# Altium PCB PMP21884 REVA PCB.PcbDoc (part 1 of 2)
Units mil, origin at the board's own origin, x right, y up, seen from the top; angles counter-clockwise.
Board outline 2378 x 1724 mil, 4 copper layers (Top Layer, Signal Layer 1, Signal Layer 2, Bottom Layer), stack 61.6 mil thick; 76 components, 35 nets, 187 pads, 142 vias.
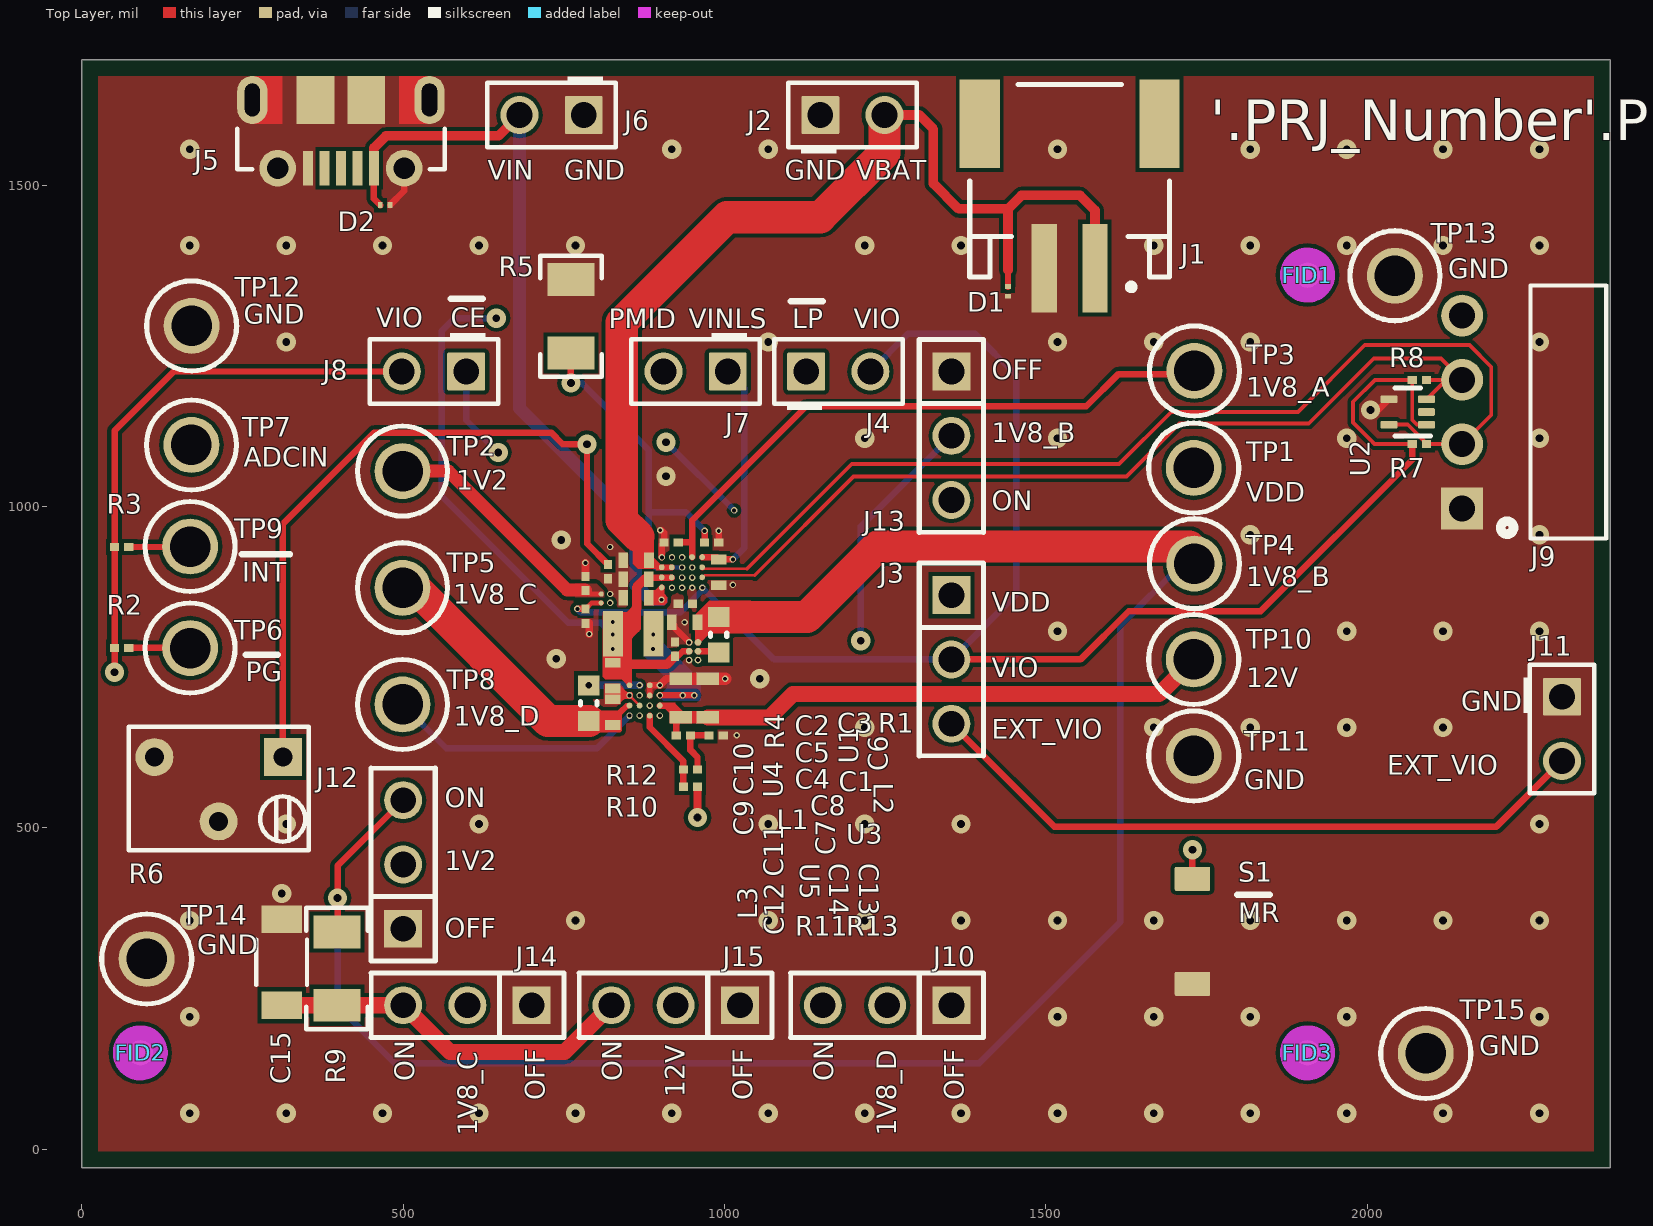
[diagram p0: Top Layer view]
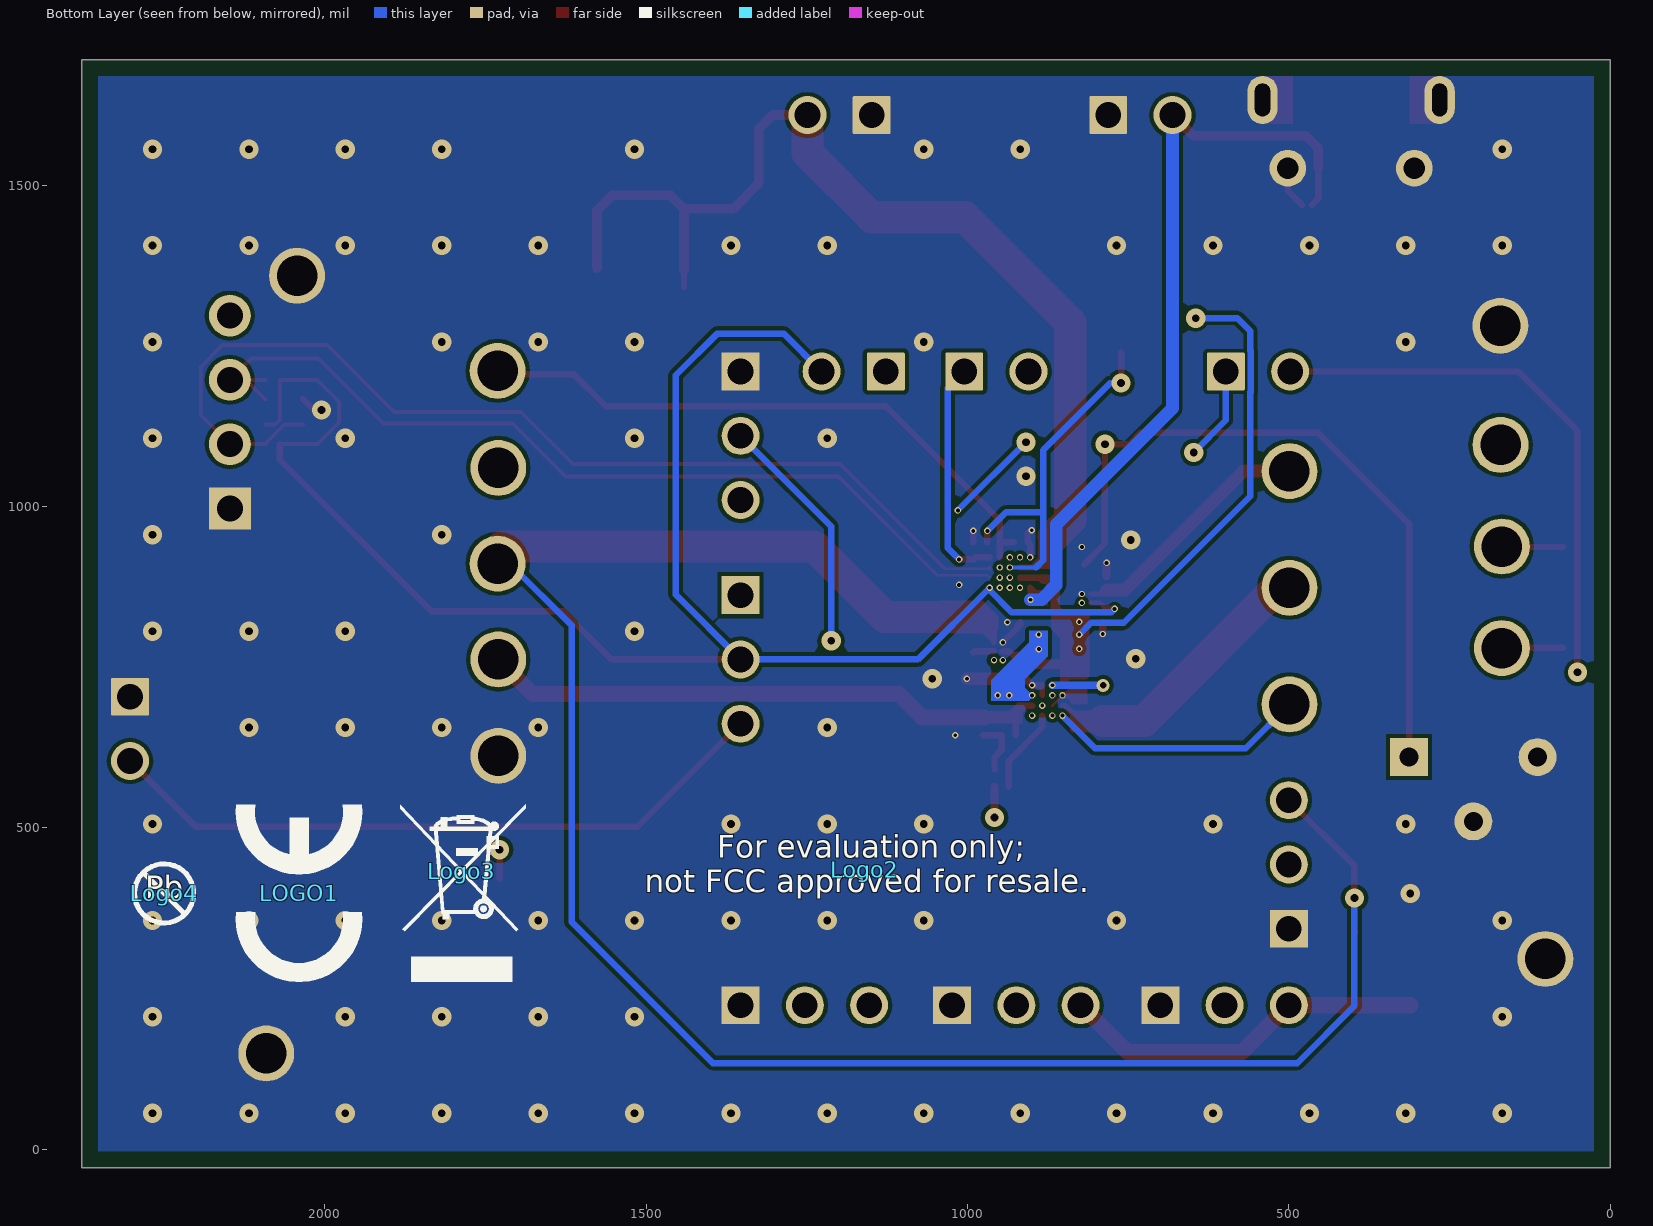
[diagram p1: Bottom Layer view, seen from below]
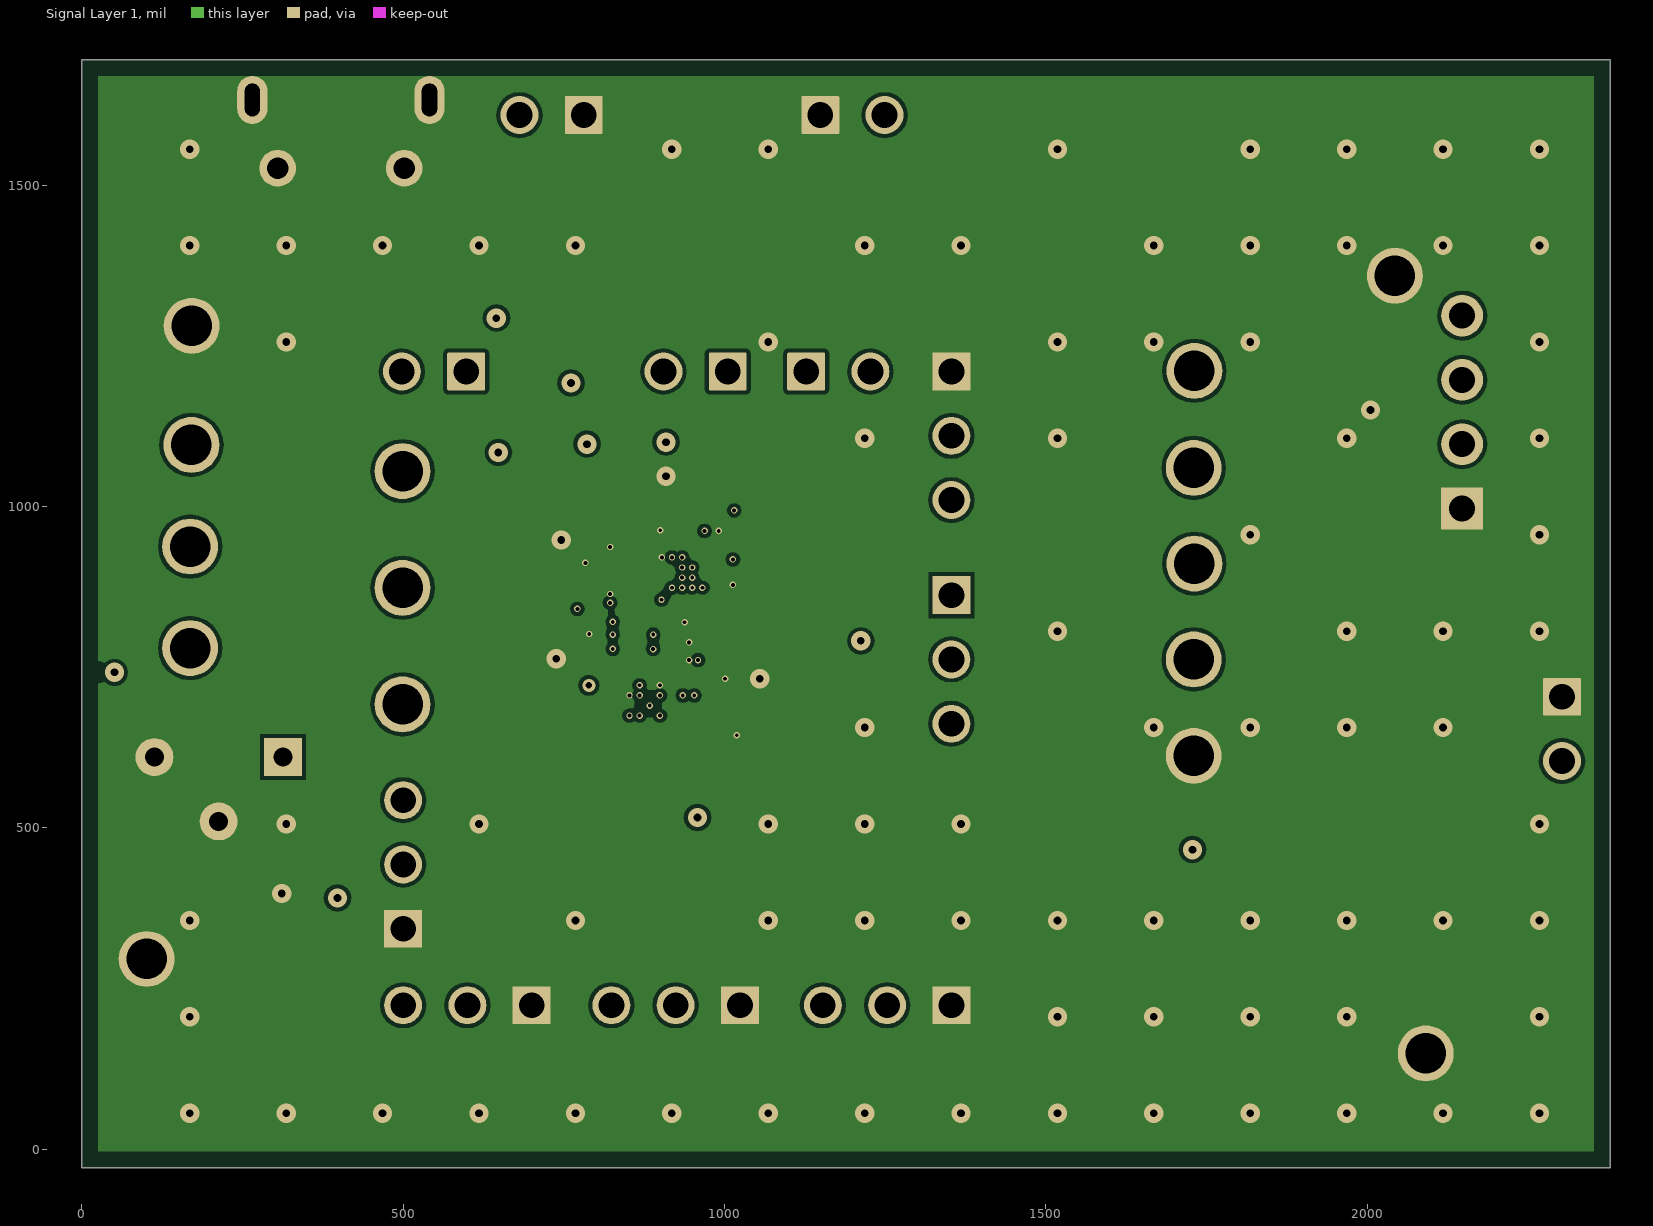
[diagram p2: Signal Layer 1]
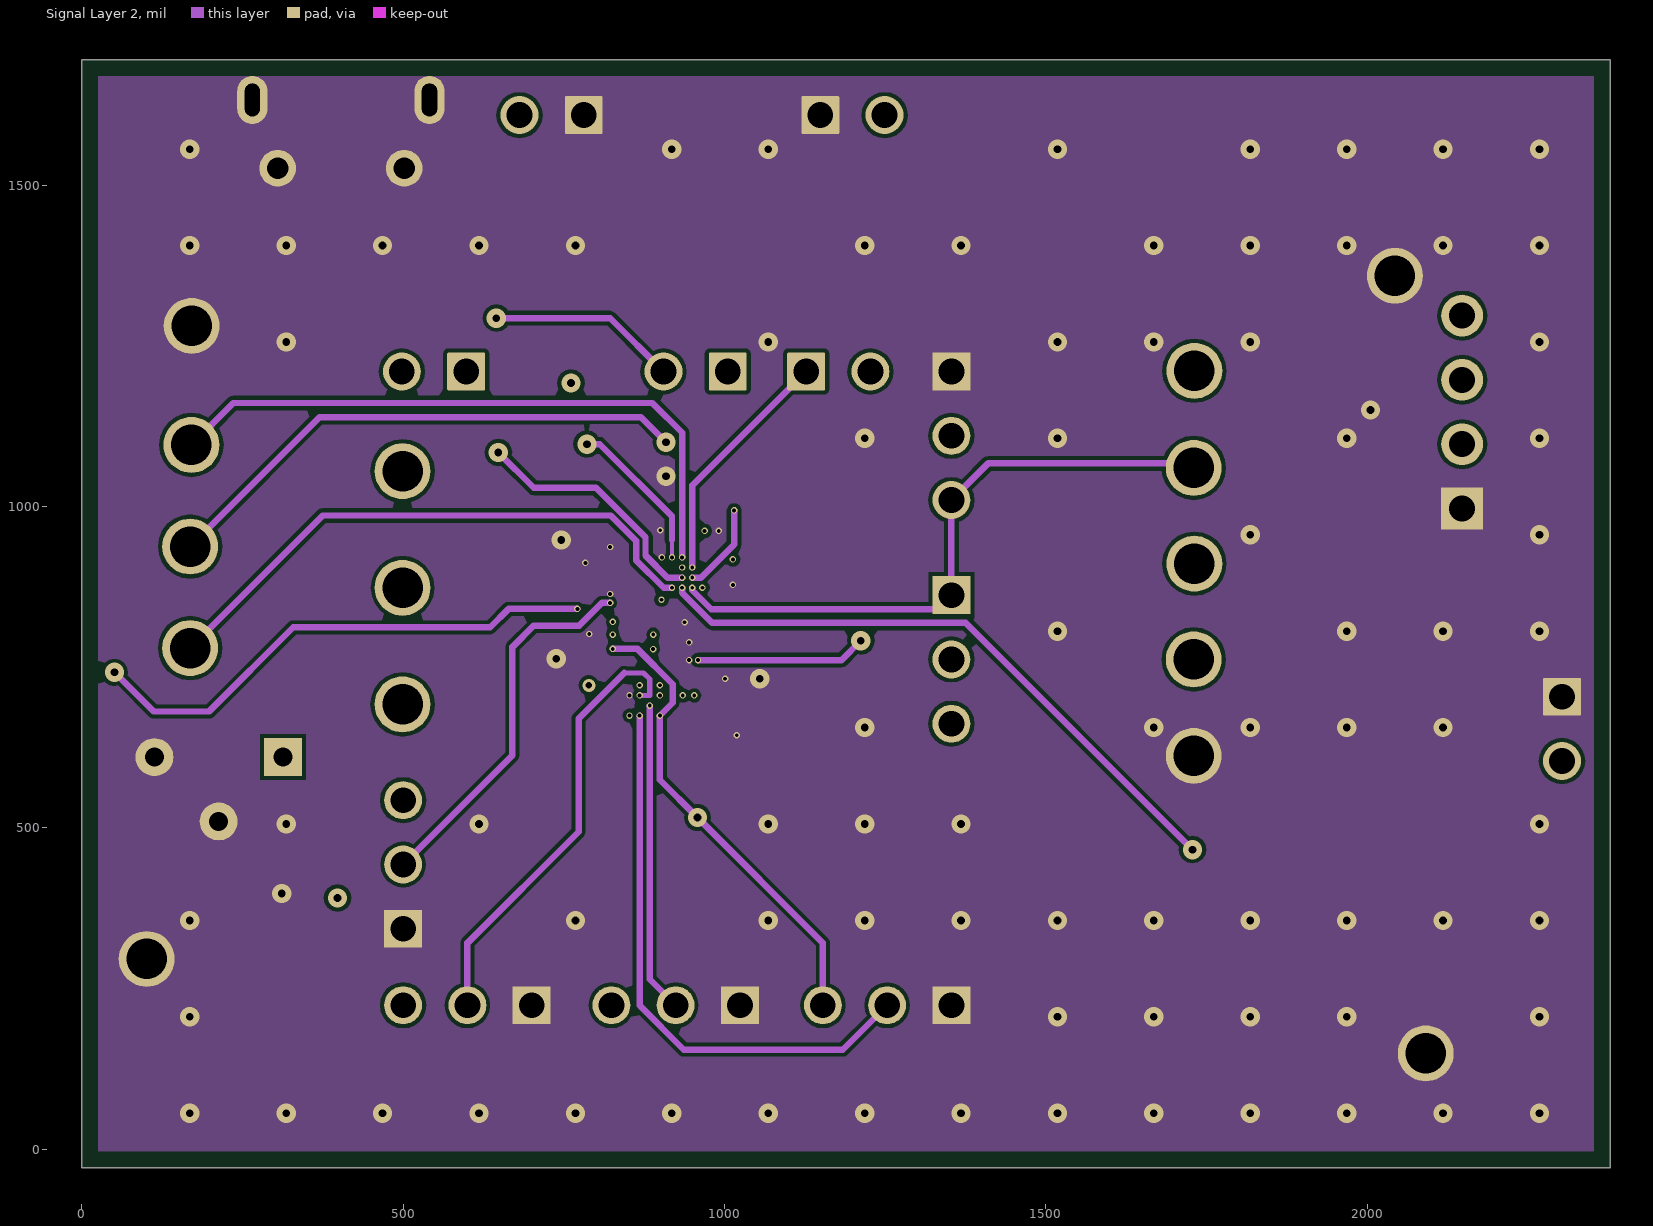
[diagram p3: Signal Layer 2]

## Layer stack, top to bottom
Top Solder: solder mask 0.4, Solder Resist, Dk 3.5
Top Layer: signal copper 1.4
Dielectric 1: prepreg 8, FR-4, Dk 4.2
Signal Layer 1: signal copper 1.4
Dielectric 2: core 40, FR-4, Dk 4.2
Signal Layer 2: signal copper 1.4
Dielectric 3: prepreg 8, FR-4, Dk 4.2
Bottom Layer: signal copper 1.4
Bottom Solder: solder mask 0.4, Solder Resist, Dk 3.5

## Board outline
0,-29 2378,-29 2378,1695 0,1695

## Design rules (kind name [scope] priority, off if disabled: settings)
AcuteAngle [All] p1: minimum=4.50000000000000E+0001 checktracksonly=FALSE
AssemblyTestPointUsage [All] p1: valid=2
BoardOutlineClearance BoardOutlineClearance_MountingHoles [OnCopper and InComponentClass('Mounting Holes')] p1: gap=25 ignorepadtopadclearanceinfootprint=FALSE
BoardOutlineClearance BoardOutlineClearance_Poly [OnCopper and InPoly] p2: gap=25 ignorepadtopadclearanceinfootprint=FALSE
BoardOutlineClearance [OnCopper and Not InComponentClass('Logo') and not InComponentClass('FiducialMark') and not InRegion(1000,500,4000,800)] p3: gap=25 ignorepadtopadclearanceinfootprint=FALSE
Clearance Clearance_GND [All vs InNet('GND') And InPolygon] p1: gap=6 ignorepadtopadclearanceinfootprint=FALSE
Clearance Clearance_Fiducial [InComponent('FID1') Or InComponent('FID2') Or InComponent('FID3')] p2: gap=0 ignorepadtopadclearanceinfootprint=FALSE
Clearance Clearance_SmallBGA [All vs InRegionRelative(800, 842, 830, 870) Or InRegionRelative(937, 754, 965, 796)] p3: gap=3.3 ignorepadtopadclearanceinfootprint=FALSE
Clearance Clearance_Keepouts [((IsTrack Or IsArc) And Not InPoly) And IsFree and IsKeepOut vs ((IsTrack Or IsArc) And Not InPoly) And IsFree and IsKeepOut] p4: gap=0 ignorepadtopadclearanceinfootprint=FALSE
Clearance Clearance_Poly [InPolygon] p5: gap=4 ignorepadtopadclearanceinfootprint=FALSE
Clearance [All] p6: gap=4 ignorepadtopadclearanceinfootprint=FALSE except(6: Arc-Hole Track-Hole SMDPad-Hole THPad-Hole Via-Hole Fill-Hole Poly-Hole Region-Hole Text-Hole)
ComponentClearance ComponentClearance_BGA [HasParameterValue('CompType', 'IC')] p1: gap=4 collisioncheckmode=3 verticalgap=10 showdistances=TRUE
ComponentClearance ComponentClearance_Cap-Resistor [HasParameterValue('CompType', 'Resistor') Or HasParameterValue('CompType', 'Capacitor') Or HasParameterValue('CompType', 'Inductor')] p2: gap=4 collisioncheckmode=3 verticalgap=0 showdistances=TRUE
ComponentClearance ComponentClearance_MountingHoles_FiducialMarks [InComponentClass('Mounting Holes') vs InComponentClass('FiducialMark')] p3: gap=50 collisioncheckmode=3 verticalgap=10 showdistances=FALSE
ComponentClearance ComponentClearance_Shunt [InComponentClass('Header') vs InComponentClass('Shunt')] p4: gap=0 collisioncheckmode=3 verticalgap=0 showdistances=FALSE
ComponentClearance ComponentClearance_Logo [InComponentClass('Logo')] p5: gap=50 collisioncheckmode=3 verticalgap=10 showdistances=FALSE
ComponentClearance ComponentClearance_ScrewToNut [(HasFootprint('NY PMS 440 0025 PH')) vs (HasFootprint('Keystone_1902C'))] p6: gap=5 collisioncheckmode=3 verticalgap=10 showdistances=FALSE
ComponentClearance ComponentClearance_MountingHoles [InComponentClass('Mounting Holes')] p7: gap=250 collisioncheckmode=3 verticalgap=100000 showdistances=FALSE
ComponentClearance ComponentClearance_SmallPassives [HasFootprint('0201*') or HasFootprint('0402*') or HasFootprint('0508') or HasFootprint('0603*') or HasFootprint('0612') or HasFootprint('0805*') or HasFootprint('0815*') or HasFootprint('0830*') or HasFootprint('1206*') or HasFootprint('1210*') or HasFootprint('1808*') or HasFootprint('1812*') or HasFootprint('1825*') or HasFootprint('2010*') or HasFootprint('2220*') or HasFootprint('2225*') or HasFootprint('2512*') or HasFootprint('2728*') or HasFootprint('3518*') vs HasFootprint('0201*') or HasFootprint('0402*') or HasFootprint('0508') or HasFootprint('0603*') or HasFootprint('0612') or HasFootprint('0805*') or HasFootprint('0815*') or HasFootprint('0830*') or HasFootprint('1206*') or HasFootprint('1210*') or HasFootprint('1808*') or HasFootprint('1812*') or HasFootprint('1825*') or HasFootprint('2010*') or HasFootprint('2220*') or HasFootprint('2225*') or HasFootprint('2512*') or HasFootprint('2728*') or HasFootprint('3518*')] p8: gap=2 collisioncheckmode=3 verticalgap=10 showdistances=FALSE
ComponentClearance ComponentClearance_THtoSMT [IsThruComponent vs IsSMTComponent] p9: gap=15 collisioncheckmode=3 verticalgap=30 showdistances=FALSE
ComponentClearance ComponentClearance_THtoTH [IsThruComponent vs IsThruComponent] p10: gap=15 collisioncheckmode=3 verticalgap=30 showdistances=FALSE
ComponentClearance [All] p11: gap=2 collisioncheckmode=3 verticalgap=10 showdistances=FALSE
DiffPairsRouting [All] p1: maxlimit=100 minlimit=10 mostfreqgap=10 toplayer_minwidth=15 toplayer_maxwidth=15 toplayer_prefwidth=15 midlayer1_minwidth=15 midlayer1_maxwidth=15 midlayer1_prefwidth=15 midlayer2_minwidth=15 midlayer2_maxwidth=15 midlayer2_prefwidth=15 bottomlayer_minwidth=15 bottomlayer_maxwidth=15 bottomlayer_prefwidth=15 maxuncoupledlength=1000
FabricationTestPointUsage TestPointUsage [All] p1: valid=2 allowmultiple=FALSE
FabricationTestpoint Testpoint [All] p1: side=3 testpointundercomponent=TRUE minsize=40 maxsize=100 preferedsize=60 minholesize=0 maxholesize=40 preferedholesize=32 testpointgrid=1 allowsidetop=TRUE allowsidebottom=TRUE usegrid=TRUE gridtolerance=0.01
FanoutControl Fanout_LCC [IsLCC] p1: bgadir=Out bgaviamode=Centered fanoutstyle=Auto fanoutdirection=Alternating viagrid=1 // Fanout_LCC (Default Rule)
FanoutControl Fanout_BGA [IsBGA] p2: bgadir=Out bgaviamode=Centered fanoutstyle=Auto fanoutdirection=Alternating viagrid=1 // Fanout_BGA (Default Rule)
FanoutControl Fanout_Default [All] p4: bgadir=Out bgaviamode=Centered fanoutstyle=Auto fanoutdirection=Alternating viagrid=1 // Fanout_Default (Default Rule)
FanoutControl Fanout_Small [(CompPinCount < 5)] p5: bgadir=Out bgaviamode=Centered fanoutstyle=Auto fanoutdirection=OutThenIn viagrid=1 // Fanout_Small (Default Rule)
HoleSize [All] p1: absolutevalues=TRUE maxlimit=251 minlimit=5 maxpercent=80.000 minpercent=20.000
HoleToHoleClearance [All] p1: gap=6 allowstackedmicrovias=TRUE
MinimumAnnularRing MinimumAnnularRing_ThermalPadVias [IsVia and InAnyComponent] p1: minimumring=5.91
MinimumAnnularRing [All] p2: minimumring=1.5
MinimumSolderMaskSliver MinimumSolderMaskSliver_Logo [InComponentClass('Logo') vs InComponentClass('Logo')] p1: minsoldermaskwidth=0.7
MinimumSolderMaskSliver [All] p2: minsoldermaskwidth=1.5
PlaneClearance PlaneClearance_GND [InNet('GND')] p1: clearance=6
PlaneClearance PlaneClearance_GND_1 [InNet('GND') And InPolygon] p2: clearance=6
PlaneClearance [All] p3: clearance=15
PlaneConnect [All] p1: planeconnectstyle=Direct reliefexpansion=10 reliefentries=4 reliefconductorwidth=10 reliefairgap=10
PolygonConnect [All] p1: connectstyle=Direct reliefconductorwidth=10 reliefentries=4 polygonreliefangle="90 Angle" airgapwidth=10
RoutingVias ThermalPadVias [IsVia and InAnyComponent] p1: holewidth=7.87 width=19.68 viastyle="Through Hole" minholewidth=7.87 minwidth=19.68 maxholewidth=12.99 maxwidth=23.62
RoutingVias [All] p2: holewidth=16 width=34 viastyle="Through Hole" minholewidth=6 minwidth=10 maxholewidth=40 maxwidth=65
SilkToBoardRegionClearance [Not ((IsComment or IsDesignator) And (Hide <> 'False')) and not InRegion(1000,500,4000,800)] p1:
SilkToSilkClearance SilkToSilkClearance_Pb-FreeLogo [(HasFootprint('Pb-Free_Overlay_Medium') OR HasFootprint('Pb-Free_Overlay_Small')) vs (HasFootprint('Pb-Free_Overlay_Medium') OR HasFootprint('Pb-Free_Overlay_Small'))] p1: silktosilkclearance=0
SilkToSilkClearance [All] p2: silktosilkclearance=0
SilkToSolderMaskClearance SilkToComponentPadClearance [IsPad and InAnycomponent] p1: minsilkscreentomaskgap=0 clearancetoexposedcopper=TRUE
SilkToSolderMaskClearance "Silk to Solder Mask Opening" [All] p2: minsilkscreentomaskgap=0 clearancetoexposedcopper=FALSE
SolderMaskExpansion [All] p1: expansion=1.97
Width [All] p1: maxlimit=100 minlimit=4 preferedwidth=10 checkconnectedcopper=TRUE
13 further rules are at their usual default settings.

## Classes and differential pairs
component class Header: J2 J3 J4 J6 J7 J8 J10 J11 J12 J13 J14 J15
component class FiducialMark: FID1 FID2 FID3

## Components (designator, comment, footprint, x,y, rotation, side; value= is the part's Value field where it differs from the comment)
C1 "GRM035R60J475ME15D" 0201L 939,848.61 r180 top value=4.7uF
C2 "CL05A105MP5NNNC" 0402S 862.43,916.19 r180 top value=1uF
C3 "CL03A225MQ3CRNC" 0201L 917,944.11 r0 top value=2.2uF
C4 "CL05A105KA5NQNC" 0402S 862.21,857.76 r180 top value=1uF
C5 "C1005X5R1A475M050BC" 0402S 862.21,886.76 r180 top value=4.7uF
C6 "CL05A105MP5NNNC" 0402S 991,897.61 r270 top value=1uF
C7 "GRM035R60J475ME15D" 0201L 923,778 r90 top value=4.7uF
C8 "GRM155R60J106ME15D" 0402S 938,820 r180 top value=10uF
C9 "GRM033R60J105MEA2D" 0201_033L 783.62,829.25 r270 top value=1uF
C10 "GRM033R60J105MEA2D" 0201_033L 783.62,880.3 r90 top value=1uF
C11 "GRM155R60J106ME15D" 0402S 825.99,736.92 r270 top value=10uF
C12 "GRM155R60J106ME15D" 0402S 826,680 r90 top value=10uF
C13 "GRM188R61E106MA73J" 0603S 974,702 r90 top value=10uF
C14 "GRM188R61E106MA73J" 0603S 932,702 r90 top value=10uF
C15 "CGA5L2X5R1H474K160AA" 1206_190 311,290.93 r90 top value=0.47uF
D1 "TPD1E6B06DPLR" DPL0002A 1441,1334.58 r90 top
D2 "TPD1E6B06DPLR" DPL0002A 472,1469 r180 top
FID1 "Fiducial" Fiducial10-20 1907,1360 r0 top
FID2 "Fiducial" Fiducial10-20 91,150 r0 top
FID3 "Fiducial" Fiducial10-20 1907,150 r0 top
J1 "S2B-PH-SM4-TB(LF)(SN)" JST_S2B-PH-SM4-TB 1537,1487 r180 top
J2 "PEC02SAAN" CONN_PEC02SAAN 1199,1609 r0 top
J3 "PEC03SAAN" CONN_PEC03SAAN 1353,762 r270 top
J4 "PEC02SAAN" CONN_PEC02SAAN 1177,1210 r0 top
J5 "105017-0001" CONN_105017-0001 403.2,1579.45 r180 top
J6 "PEC02SAAN" CONN_PEC02SAAN 731,1609 r180 top
J7 "PEC02SAAN" CONN_PEC02SAAN 955,1210 r180 top
J8 "PEC02SAAN" CONN_PEC02SAAN 548,1210 r180 top
J9 "22/05/3041" CONN_22-05-3041 2372,1147 r90 top
J10 "PEC03SAAN" CONN_PEC03SAAN 1253,224 r180 top
J11 "PEC02SAAN" CONN_PEC02SAAN 2303,654 r270 top
J12 "PEC03SAAN" CONN_PEC03SAAN 500,443 r90 top
J13 "PEC03SAAN" CONN_PEC03SAAN 1353,1110 r270 top
J14 "PEC03SAAN" CONN_PEC03SAAN 600,224 r180 top
J15 "PEC03SAAN" CONN_PEC03SAAN 924,224 r180 top
L1 "DFE201610E-100M=P2" DFE201610E 858,802 r180 top value=10uH
L2 "DFE18SANR47MG0L" 0603L 990.72,800.45 r90 top value=470nH
L3 "LQM18PN2R2MGHD" 0603L 789,694 r270 top value=2.2uH
LOGO1 "CE Mark" CE_Mark_5mm 2040,398 r90 bottom (schematic designator Logo1)
Logo2 "FCC disclaimer" FCC_disclaimer_stacked 1160,434.9 r180 bottom
Logo3 "WEEE logo" WEEE_Minimum 1787,432.45 r180 bottom
Logo4 "Pb-Free Symbol" Pb-Free_Overlay_Small 2250,398 r180 bottom
R1 "RC0201JR-0712KL" 0201L 979.98,944 r0 top value=12k
R2 "RC0201JR-0710KL" 0201L 62.02,780 r0 top value=10k
R3 "RC0201JR-0710KL" 0201L 62.02,937 r0 top value=10k
R4 "RC0201FR-0710KL" 0201L 818.62,898.63 r270 top value=10.0k
R5 "RC1206FR-0759KL" 1206 761,1296 r270 top value=59.0k
R6 "3266W-1-104LF" TRIM_3266W 313,610 r270 top value=100k
R7 "RC0201JR-0710KL" 0201L 2080.98,1097 r180 top value=10k
R8 "RC0201JR-0710KL" 0201L 2080.98,1197 r0 top value=10k
R9 "CRCW12066K04FKEA" 1206 397,281.09 r270 top value=6.04k
R10 "CRCW02010000Z0ED" 0201L 946.98,564 r0 top value=0
R11 "RC0201JR-07430KL" 0201L 935.98,644 r180 top value=430k
R12 "CRCW02010000Z0ED" 0201L 946.98,591 r180 top value=0
R13 "RC0201FR-0782KL" 0201L 987,644 r180 top value=82.0k
S1 "TL1015AF160QG" SW_TL1015AF160QG 1728,339 r90 top
TP1 "5010" Keystone5010 1730,1060 r0 top
TP2 "5010" Keystone5010 499,1055 r0 top
TP3 "5010" Keystone5010 1731,1211 r0 top
TP4 "5010" Keystone5010 1731,911 r0 top
TP5 "5010" Keystone5010 499,873.5 r0 top
TP6 "5012" Keystone5012 168.6,779.72 r180 top
TP7 "5012" Keystone5012 170.6,1095.72 r180 top
TP8 "5010" Keystone5010 499,692 r0 top
TP9 "5012" Keystone5012 168.6,937.72 r180 top
TP10 "5010" Keystone5010 1730,762 r0 top
TP11 "5011" Keystone5011 1730,612 r0 top
TP12 "5011" Keystone5011 171,1281 r0 top
TP13 "5011" Keystone5011 2043,1359 r0 top
TP14 "5011" Keystone5011 101,296 r0 top
TP15 "5011" Keystone5011 2091,149 r0 top
U1 "BQ25150YFPR" YFP0020ACAC 933.72,897.62 r90 top
U2 "TPD2E001IDRLRQ1" DRL0005A 2062.98,1147 r180 top
U3 "TPS62802YKAR" YKA0006ACAC 951.83,774.78 r0 top
U4 "TPS7A0512PYKAR" YKA0004ACAC 815,857 r90 top
U5 "TPS62770YFPR" YFP0016ACAC 875.75,698.16 r270 top

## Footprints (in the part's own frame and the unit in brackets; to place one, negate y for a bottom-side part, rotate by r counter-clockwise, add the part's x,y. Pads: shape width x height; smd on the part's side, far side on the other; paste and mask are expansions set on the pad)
0201_033L [mm] "0201"
  rect 0.36x0.32 smd mask+0.048: 1(-0.28,0) 2(0.28,0)
  body extent -0.31,-0.16 0.31,0.16, height 0.33
0201L [mm] "Data from Kemet datasheet CC101_COM dated 7/28/11"
  rect 0.36x0.32 smd mask+0.048: 1(-0.28,0) 2(0.28,0)
  body extent -0.31,-0.16 0.31,0.16, height 0.26
0402S [mil] "Based on C0402S footprint from PADS legacy"
  rect 15x24 smd: 1(-20,0) 2(20,0)
  body extent -22,-12 22,12, height 24
0603L [mm] "0603 from SM-752 data"
  rect 0.8x0.85 smd: 1(-0.7,0) 2(0.7,0)
  silkscreen extent -0.07,-0.33 0.07,0.33, body extent -0.87,-0.47 0.87,0.47, height 1
0603S [mil] "0603 from SM-752 data"
  rect 20x35 smd: 1(-30,0) 2(30,0)
  body extent -34,-19 34,19, height 39
1206 [mm] "1206 from SM-752 data"
  rect 1.3x1.85 smd: 1(-1.45,0) 2(1.45,0)
  silkscreen extent -2.4,-1.21 2.4,1.21, body extent -1.7,-0.9 1.7,0.9, height 1.35
1206_190 [mm] "1206_190"
  rect 1.1x1.6 smd: 1(-1.7,0) 2(1.7,0)
  silkscreen extent -0.9,-1 0.9,1, body extent -1.75,-0.95 1.75,0.95, height 1.9
CE_Mark_5mm [mil] "Minimum text height for CE Mark"
  silkscreen extent -138,-98 138,98
CONN_22-05-3041 [mm] "MOLEX"
  rect 1.65x1.65 hole 1.02: 1(-3.81,5.7)
  round 1.65 hole 1.02: 2(-1.27,5.7) 3(1.27,5.7) 4(3.81,5.7)
  silkscreen extent -5,0 5,4.18, body extent -5,-6.91 5,6.02, height 6.37
CONN_105017-0001 [mm] "Molex Micro USB-B"
  rect 0.4x1.35 smd: 1(-1.3,1.35) 2(-0.65,1.35) 3(0,1.35) 4(0.65,1.35) 5(1.3,1.35)
  oval 1.2x1.9 hole 0.6 slot 1.3 at 90 deg: 6(-3.5,-1.35) 9(3.5,-1.35)
  rect 1.5x1.9 smd: 7(-1,-1.35) 8(1,-1.35)
  round 1.45 hole 0.85: 10(2.5,1.35) 11(-2.5,1.35)
  Top Layer region: 3.5,-0.4 2.3,-0.4 2.3,-2.3 3.5,-2.3
  Top Layer region: -3.5,-2.3 -2.3,-2.3 -2.3,-0.4 -3.5,-0.4
  silkscreen extent -4.1,-0.2 4.1,1.4, body extent -4.1,-3.93 4.1,1.5, height 2.72
CONN_PEC02SAAN [mm] "SULLINS"
  rrect7% 1.5x1.5 hole 1.016: 1(-1.27,0)
  round 1.5 hole 1.016: 2(1.27,0)
  silkscreen extent -2.54,-1.52 2.54,1.27, body extent -2.54,-1.27 2.54,1.27, height 8.38
CONN_PEC03SAAN [mm] "SULLINS"
  rect 1.5x1.5 hole 1.016: 1(-2.54,0)
  round 1.5 hole 1.016: 2(0,0) 3(2.54,0)
  silkscreen extent -3.81,-1.27 3.81,1.27, body extent -3.84,-1.3 3.84,1.3, height 8.38
DFE201610E [mm] "MuRata"
  rect 0.8x1.8 smd: 1(0.8,0) 2(-0.8,0)
  body extent -1.1,-0.9 1.1,0.9, height 1
DPL0002A [mm] "R-PX2SON-N2"
  rect 0.18x0.25 smd: 1(-0.193,0)
  rect 0.19x0.25 smd: 2(0.193,0)
  body extent -0.32,-0.17 0.32,0.17, height 0.32
DRL0005A [mm] "SOTFL, 5-Flat Leads, Body 1.2x1.6x0.6mm, Pitch 0.5mm, TI recommended"
  rrect33% 0.67x0.3 smd: 1(-0.74,0.5) 2(-0.74,0) 3(-0.74,-0.5) 4(0.74,-0.5) 5(0.74,0.5)
  silkscreen extent -0.9,-0.95 0.5,0.95, body extent -0.85,-0.85 0.85,0.85, height 0.62
FCC_disclaimer_stacked [mil]
Fiducial10-20 [mm]
  round 1 smd mask+0.5: 1(0,0)
  Top Layer keep-out circle w1.178: c0,0 r0.5
JST_S2B-PH-SM4-TB [mm] "JST Sales America Inc"
  rect 1x3.5 smd paste+0 mask+0.05: 1(-1,2.95) 2(1,2.95)
  rect 1.6x3.5 smd paste+0 mask+0.05: M1(-3.55,-2.75) M2(3.55,-2.75)
  silkscreen extent -3.95,-4.3 3.95,3.79, body extent -3.95,-4.3 3.95,4.3, height 5.62
Keystone5010 [mil] "Keystone Multipurpose loops"
  round 87 hole 63: 1(0,0)
  silkscreen extent -70,-70 70,70, body extent -63,-63 63,62, height 319
Keystone5011 [mil] "Keystone Multipurpose loops"
  round 87 hole 63: 1(0,0)
  silkscreen extent -70,-70 70,70, body extent -63,-63 63,62, height 319
Keystone5012 [mil] "Keystone Multipurpose loops"
  round 87 hole 63: 1(0,0)
  silkscreen extent -70,-70 70,70, body extent -63,-63 63,62, height 319
Pb-Free_Overlay_Small [mil]
  silkscreen extent -46,-46 46,46
SW_TL1015AF160QG [mm] "E-Switch"
  rrect11% 0.95x1.4 smd: 1(-2.075,0) 2(2.075,0)
  body extent -2.3,-1.5 2.3,1.5, height 2
TRIM_3266W [mm] "Bourns 3266W series REV 08/10"
  rect 1.5x1.5 hole 0.75: 1(0,0)
  round 1.5 hole 0.75: 2(2.54,-2.54) 3(0,-5.08)
  silkscreen extent -1.2,-6.09 3.68,1.01, body extent -1.2,-6.09 3.68,1.01, height 8.45
WEEE_Minimum [mil] "WEEElie bin"
  silkscreen extent -95,-172 99,104
YFP0016ACAC [mm] "BGA, 16-Leads, Body 1.652x1.652mm, Pitch 0.4mm"
  round 0.23 smd paste-0.13 mask+0.038: A1(-0.6,0.6) A2(-0.2,0.6) A3(0.2,0.6) A4(0.6,0.6) B1(-0.6,0.2) B2(-0.2,0.2) B3(0.2,0.2) B4(0.6,0.2) C1(-0.6,-0.2) C2(-0.2,-0.2) C3(0.2,-0.2) C4(0.6,-0.2) D1(-0.6,-0.6) D2(-0.2,-0.6) D3(0.2,-0.6) D4(0.6,-0.6)
  body extent -0.83,-0.83 0.83,0.83, height 0.63
YFP0020ACAC [mm] "BGA, 20-Leads, Body 1.65x2.05mm, Pitch 0.4mm"
  round 0.23 smd paste-0.13 mask+0.038: A1(-0.6,0.8) A2(-0.2,0.8) A3(0.2,0.8) A4(0.6,0.8) B1(-0.6,0.4) B2(-0.2,0.4) B3(0.2,0.4) B4(0.6,0.4) C1(-0.6,0) C2(-0.2,0) C3(0.2,0) C4(0.6,0) D1(-0.6,-0.4) D2(-0.2,-0.4) D3(0.2,-0.4) D4(0.6,-0.4) E1(-0.6,-0.8) E2(-0.2,-0.8) E3(0.2,-0.8) E4(0.6,-0.8)
  body extent -0.82,-1.02 0.82,1.02, height 0.5
YKA0004ACAC [mm] "DSBGA, 4-Balls, Body 0.75x0.75mm, Pitch 0.35mm"
  round 0.2 smd paste-0.12 mask+0.038: A1(-0.175,0.175) A2(0.175,0.175)
  round 0.2 smd paste-0.12 mask+0.032: B1(-0.175,-0.175) B2(0.175,-0.175)
  body extent -0.38,-0.38 0.38,0.38, height 0.45
YKA0006ACAC [mm] "BGA, 6-Leads, Body 1.09x0.74mm, Pitch 0.35mm"
  round 0.265 smd paste-0.12 mask-0.032: A1(-0.175,0.35) C1(-0.175,-0.35) C2(0.175,-0.35)
  round 0.265 smd paste-0.12 mask+0: A2(0.175,0.35) B1(-0.175,0) B2(0.175,0)
  body extent -0.37,-0.55 0.37,0.55, height 0.45

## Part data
C1 C7: library part CMP-0009780-1, "CAP, CERM, 4.7 uF, 6.3 V, +/- 20%, X5R, 0201", Cap_Case=0201, Manufacturer=MuRata, Supplier Part Number 1=490-13230-1-ND, TempCo=X5R, Tolerance_%=20%, Value1=Unknown, Value2=6.3V, ValueDisplayed=4.7uF
C2 C6: library part CMP-0085849-1, "CAP, CERM, 1 µF, 10 V,+/- 20%, X5R, 0402", Cap_Case=0402, Manufacturer="Samsung Electro-Mechanics", Supplier Part Number 1=1276-1448-1-ND, TempCo=X5R, Tolerance_%=20%, Value2=10V, ValueDisplayed=1µF
C3: library part CMP-0009657-3, "CAP, CERM, 2.2 uF, 6.3 V, +/- 20%, X5R, 0201", Cap_Case=0201, Manufacturer="Samsung Electro-Mechanics", TempCo=X5R, Tolerance_%=20%, Value1=Unknown, Value2=6.3V, ValueDisplayed=2.2uF
C4: library part CMP-0085848-1, "CAP, CERM, 1 µF, 25 V,+/- 10%, X5R, 0402", Cap_Case=0402, Manufacturer="Samsung Electro-Mechanics", TempCo=X5R, Tolerance_%=10%, Value2=25V, ValueDisplayed=1µF
C5: library part CMP-0006269-2, "CAP, CERM, 4.7 uF, 10 V, +/- 20%, X5R, 0402", Cap_Case=0402, Manufacturer=TDK, Supplier Part Number 1=445-8023-1-ND, TempCo=X5R, Tolerance_%=20%, Value1=Unknown, Value2=10V, ValueDisplayed=4.7uF
C8 C11 C12: library part CMP-0006534-2, "CAP, CERM, 10 uF, 6.3 V, +/- 20%, X5R, 0402", Cap_Case=0402, Manufacturer=MuRata, TempCo=X5R, Tolerance_%=20%, Value1=Unknown, Value2=6.3V, ValueDisplayed=10uF
C9 C10: library part CMP-0009692-3, "CAP, CERM, 1 uF, 6.3 V, +/- 20%, X5R, 0201", Cap_Case=0201, Manufacturer=MuRata, Supplier Part Number 1=490-7229-1-ND, TempCo=X5R, Tolerance_%=20%, Value1=Unknown, Value2=6.3V, ValueDisplayed=1uF
C13 C14: library part CMP-0007344-5, "CAP, CERM, 10 uF, 25 V, +/- 20%, X5R, 0603", Cap_Case=0603, Manufacturer=MuRata, Supplier Part Number 1=490-12737-1-ND, TempCo=X5R, Tolerance_%=20%, Value1=Unknown, Value2=25V, ValueDisplayed=10uF
C15: library part CMP-0008774-2, "CAP, CERM, 0.47 uF, 50 V, +/- 10%, X5R, AEC-Q200 Grade 3, 1206_190", Cap_Case=1206, Manufacturer=TDK, Supplier Part Number 1=445-12875-1-ND, TempCo=X5R, Tolerance_%=10%, Value1=Unknown, Value2=50V, ValueDisplayed=0.47uF
D1 D2: library part CMP-0750037-1, "Single-Channel ESD in 0201 Package With 6pF Capacitance and 6V Breakdown, DPL0002A (X2SON-2)", Alternate Manufacturer="Texas Instruments", Alternate PartNumber=TPD1E6B06DPLT, Operating Temperature Range="-40 to 125 C", Rating=Catalog
FID1 FID2 FID3: library part CMP-0077181-1, "Fiducial mark.  There is nothing to buy or mount.", Manufacturer=N/A
J1: library part CMP-0074984-1, "Header (shrouded), 2mm, 2x1, R/A, SMT", Manufacturer="JST Manufacturing", Supplier Part Number 1=455-1749-1-ND
J2 J4 J6 J7 J8 J11: library part CMP-0002337-1, "Header, 100mil, 2x1, Tin, TH", Color=Black, Current_A=3A, Manufacturer="Sullins Connector Solutions", Supplier Part Number 1=S1012E-02-ND, Voltage_V=1.8kV
J3 J10 J12 J13 J14 J15: library part CMP-0002338-1, "Header, 100mil, 3x1, Tin, TH", Color=Black, Current_A=3A, Manufacturer="Sullins Connector Solutions", Supplier Part Number 1=S1012E-03-ND, Voltage_V=1.8kV
J5: library part CMP-0055293-1, "Connector, Receptacle, Micro-USB Type B, R/A, Bottom Mount SMT", Manufacturer=Molex, Supplier Part Number 1=WM1399CT-ND
J9: library part CMP-0055187-1, "Header (friction lock), 100mil, 4x1, R/A, TH", Manufacturer=Molex, Supplier Part Number 1=WM4302-ND
L1: library part CMP-0080880-2, "Inductor, Shielded, Metal Composite, 10 µH, 0.65 A, 0.78 ohm, SMD", Manufacturer=MuRata, PartNumber=DFE201610E-100M{}P2, Supplier Part Number 1=DFE201610E-100M{}P2-ND, Value1="0.78 ohm", Value2=0.65A, ValueDisplayed=10µH
L2: library part CMP-0078483-1, "Inductor, Shielded, Metal Composite, 470 nH, 2.6 A, 0.054 ohm, SMD", Manufacturer=MuRata, Supplier Part Number 1=490-16581-1-ND, Value1="0.054 ohm", Value2=2.6A, ValueDisplayed=470nH
L3: library part CMP-0058736-1, "Inductor, Ferrite, 2.2 uH, 0.25 A, 0.2 ohm, SMD", Manufacturer=MuRata, Value1="0.2 ohm", Value2=0.25A, ValueDisplayed=2.2uH
LOGO1: library part CMP-0074844-1
Logo2: library part CMP-0074847-1, "FCC_disclaimer"
Logo3: library part CMP-0074769-1
Logo4: library part CMP-0074839-1
R1: library part CMP-0027028-1, "RES, 12 k, 5%, 0.05 W, 0201", Manufacturer="Yageo America", Power_W=50mW, Supplier Part Number 1=311-12KNCT-ND, TempCo="200 ppm/C", Tolerance_%=5%, Value2=0.05W, Value_Code=12k0, ValueDisplayed=12k
R2 R3 R7 R8: library part CMP-0027019-1, "RES, 10 k, 5%, 0.05 W, 0201", Manufacturer="Yageo America", Power_W=50mW, Supplier Part Number 1=311-10KNCT-ND, TempCo="200 ppm/C", Tolerance_%=5%, Value2=0.05W, Value_Code=10k0, ValueDisplayed=10k
R4: library part CMP-0027304-2, "RES, 10.0 k, 1%, 0.05 W, 0201", Manufacturer="Yageo America", Power_W=50mW, Supplier Part Number 1=311-10.0KMCT-ND, TempCo="200 ppm/C", Tolerance_%=1%, Value2=0.05W, Value_Code=10k0, ValueDisplayed=10.0k
R5: library part CMP-0018387-2, "RES, 59.0 k, 1%, 0.25 W, 1206", Manufacturer="Yageo America", Power_W=250mW, Supplier Part Number 1=311-59.0KFRCT-ND, TempCo="100 ppm/C", Tolerance_%=1%, Value2=0.25W, Value_Code=59k0, ValueDisplayed=59.0k
R6: library part CMP-0002070-1, "Trimmer, 100k ohm, 0.25W, TH", Manufacturer=Bourns, Supplier Part Number 1=3266W-104LF-ND
R9: library part CMP-0017127-3, "RES, 6.04 k, 1%, 0.25 W, AEC-Q200 Grade 0, 1206", Manufacturer=Vishay-Dale, Power_W=250mW, Supplier Part Number 1=541-6.04KFCT-ND, TempCo="100 ppm/C", Tolerance_%=1%, Value2=0.25W, Value_Code=6k04, ValueDisplayed=6.04k
R10 R12: library part CMP-0027008-4, "RES, 0, 5%, 0.05 W, 0201", Manufacturer=Vishay-Dale, Power_W=50mW, Supplier Part Number 1=72M6743, TempCo=ppm/C, Tolerance_%=5%, Value2=0.05W, Value_Code=0000, ValueDisplayed=0
R11: library part CMP-0027122-1, "RES, 430 k, 5%, 0.05 W, 0201", Manufacturer="Yageo America", Power_W=50mW, Supplier Part Number 1=YAG2899CT-ND, TempCo="200 ppm/C", Tolerance_%=5%, Value2=0.05W, Value_Code=430k
R13: library part CMP-0027892-1, "RES, 82.0 k, 1%, 0.05 W, 0201", Manufacturer="Yageo America", Power_W=50mW, Supplier Part Number 1=YAG2816CT-ND, TempCo="200 ppm/C", Tolerance_%=1%, Value2=0.05W, Value_Code=82k0, ValueDisplayed=82.0k
S1: library part CMP-0002143-3, "Switch, Tactile, SPST-NO, 0.05A, 12V, SMT", CurrentRating_mA=50A, Manufacturer=E-Switch, Supplier Part Number 1=EG4344CT-ND
TP1 TP2 TP3 TP4 TP5 TP8 TP10: library part CMP-0055147-1, "Test Point, Multipurpose, Red, TH", Color=Red, Manufacturer=Keystone, Supplier Part Number 1=36-5010-ND
TP6 TP7 TP9: library part CMP-0055149-1, "Test Point, Multipurpose, White, TH", Color=White, Manufacturer=Keystone, Supplier Part Number 1=36-5012-ND
TP11 TP12 TP13 TP14 TP15: library part CMP-0055148-1, "Test Point, Multipurpose, Black, TH", Color=Black, Manufacturer=Keystone, Supplier Part Number 1=36-5011-ND
U1: library part CMP-0077167-2, "BQ25150YFP, YFP0020ACAC (DSBGA-20)", Alternate Manufacturer="Texas Instruments", Alternate PartNumber=BQ25150YFPT
U2: library part CMP-0043127-2, "Automotive Catalog Low-Capacitance + / - 15 kV ESD-Protection Array for High-Speed Data Inter, 2 Channels, -40 to +85 degC, 5-pin SOT (DRL), Green (RoHS & no Sb/Br)", Breakdown Voltage(Min)(V)=11, IO Capacitance(Typ)(pF)=1.5, IO Leakage Current(nA)=1, Manufacturer="Texas Instruments"
U3: library part CMP-0077660-3, "Tiny High Frequency Ultra-low Iq Step-Down Converter, YKA0006ACAC (DSBGA-6)", Alternate Manufacturer="Texas Instruments", Alternate PartNumber=TPS62802YKAT
U4: library part CMP-0100015-2, "1µA, ultra-low Iq, 200mA low-dropout (LDO) regulator in a small-size package, YKA0004ACAC (DSBGA-4)", Alternate Manufacturer="Texas Instruments", Operating Temperature Range="-40 to 125 C", Rating=Catalog
U5: library part CMP-0074186-1, "Tiny Single-chip Dual Solution with 360nA Iq Buck and up to 15V Boost in WCSP, YFP0016ACAC (DSBGA-16)", Alternate Manufacturer="Texas Instruments", Alternate PartNumber=TPS62770YFPT

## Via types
v1: diameter 30, hole 12, Top Layer to Bottom Layer, tented both sides, 95 vias
v2: diameter 10, hole 6, Top Layer to Bottom Layer, tented bottom, 30 vias
v3: diameter 10, hole 6, Top Layer to Bottom Layer, tented both sides, 16 vias
v4: diameter 20, hole 10, Top Layer to Bottom Layer, tented bottom, 1 vias

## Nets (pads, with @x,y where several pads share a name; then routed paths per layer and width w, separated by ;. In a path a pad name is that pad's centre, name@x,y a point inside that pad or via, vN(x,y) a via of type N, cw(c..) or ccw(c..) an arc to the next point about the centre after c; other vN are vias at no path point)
1V2: C10.1 TP2.1 U4.A2 | length 388.1
  Top Layer w8: C10.1@783.62,869.28 789.01,863.89 U4.A2@808.11,863.89
  Top Layer w20: TP2.1@499,1055 570.37,1055 755.13,870.24 782.99,870.24 C10.1@783.62,869.61
1V8_A: C3.2 TP3.1 U1.D4 | length 955
  Top Layer w10: C3.2@928.02,944.11 949.75,944.11 ; U1.D4@949.75,920.85 949.75,944.11 ; TP3.1@1731,1206 1613,1206 1563,1156 1127,1156 949.75,978.75 949.75,944.11
1V8_B: C8.1 J12.3 L2.2 R9.1 TP4.1 U3.A2 | length 3152.9
  Top Layer w10: R9.1@397,338.17 398,339.17 v1(398,391) 398,441 J12.3@500,543 ; C8.1@958,820 958.72,819.28 U3.A2@958.72,788.56
  Top Layer w50: 1036,828 1128.26,828 1238.25,938 1723,938 TP4.1@1731,930
  Bottom Layer w10: v1(398,391) 398,223 487,134 1396,134 1616,354 1616,815 1712,911 TP4.1@1731,911
1V8_C: C12.1 L3.2 TP5.1 U5.D3 | length 419.1
  Top Layer w8: C12.1@826,660 826,668.04 848.25,690.29 U5.D3@852.12,690.29
  Top Layer w50: TP5.1@499,873.5 518.5,873.5 725.56,666.44 L3.2@789,666.44
1V8_D: TP8.1 U5.D4 | length 402.2
  Bottom Layer w10: TP8.1@499,692 567,624 801.58,624 v2(852.12,674.54)
12V: C13.1 C14.1 R11.2 TP10.1 U5.A3 | length 939.4
  Top Layer w10: U5.A3@899.37,690.29 919.37,690.29 931.62,678.04 931.62,669.04 924.95,662.37 R11.2@924.95,644 ; C13.1@974,672 C13.1@979.69,666.31
  Top Layer w20: C14.1@932,672 C13.1@974,672
  Top Layer w25: C13.1@974,672 1070.5,672 1106.53,708.03 1676.03,708.03 TP10.1@1730,762 ; TP10.1@1714.5,777.5 TP10.1@1730,793
EXT_VIO: J3.3 J11.2 | length 1058.5
  Top Layer w10: J3.3@1353,662 1513,502 2201,502 J11.2@2303,604
GND: C1.2 C2.2 C3.1 C4.2 C5.2 C6.2 C7.2 C8.2 C9.2 C10.2 C11.2 C12.2 C13.2 C14.2 C15.2 D1.1 D2.1 J1.2 J2.1 J5.5 J5.6 J5.7 J5.8 J5.9 J5.10 J5.11 J6.1 J9.1 J10.1 J11.1 J12.1 J13.1 J14.1 J15.1 R1.2 R4.2 R5.1 R6.2 R6.3 R13.1 S1.1 TP11.1 TP12.1 TP13.1 TP14.1 TP15.1 U1.A4 U2.4 U3.A1 U3.C1 U4.B2 U5.A1 U5.B1 U5.B2 U5.C3 U5.D2 | length 414.1
  Top Layer w4: v2(852.12,706.04) U5.C3@867.87,690.29
  Top Layer w6: C3.1@905.32,944.76 C3.1@905.98,945.42
  Top Layer w8: U5.B2@883.62,706.04 U5.B1@883.62,721.78
  Top Layer w10: D2.1@479.58,1469 501.63,1491.05 J5.11@501.63,1526.3 ; U5.B1@883.62,721.78 v2(899.37,721.78) ; v3(900,963) 902.23,963 905.98,959.25 C3.1@905.98,945.42 ; v2(902.51,920.85) 902.51,940.64 C3.1@905.98,944.11 ; C8.2@918,820 918,815.72 919.72,814.01 919.72,817.45 922.19,814.97 922.19,811.31 v2(944.94,788.56) ; R1.2@991,944 v3(991,962) ; v1(2005,1150) 2017.16,1150 2024.16,1157 2033.16,1166 U2.4@2033.84,1166.68
  Top Layer w12: C10.2@783.62,891.33 v3(783.62,912.2) ; v3(789.62,801.61) C9.2@789.62,818.56 ; v2(899.37,721.78) 909.58,732 C14.2@932,732
  Top Layer w20: C14.2@932,732 C13.2@974,732 v3(1001,732)
  other v1: 168,56 318,56 468,56 618,56 768,56 918,56 1068,56 1218,56 1368,56 1518,56 1668,56 1818,56 1968,56 2118,56 2268,56 168,206 1518,206 1668,206 1818,206 1968,206 2268,206 168,356 768,356 1068,356 1218,356 1368,356 1518,356 1668,356 1818,356 1968,356 2118,356 2268,356 311,398 318,506 618,506 1068,506 1218,506 1368,506 2268,506 1218,656 1668,656 1818,656 1968,656 2118,656 1055,732 738,763 1518,806 1968,806 2118,806 2268,806 746,947.72 1818,956 2268,956 909,1047 1218,1106 1518,1106 1968,1106 2268,1106 318,1256 1068,1256 1518,1256 1668,1256 1818,1256 2268,1256 168,1406 318,1406 468,1406 618,1406 768,1406 1218,1406 1368,1406 1668,1406 1818,1406 1968,1406 2118,1406 2268,1406 168,1556 918,1556 1068,1556 1518,1556 1818,1556 1968,1556 2118,1556 2268,1556
  other v2: 944.94,761 821.89,863.89
  other v3: 1019,644 938,820 1013,878 822,937
NetC6_1: C6.1 J7.1 U1.E4 | length 359.5
  Top Layer w10: U1.E4@965.5,920.85 987.76,920.85 C6.1@991,917.61 v3(1013,917.61)
  Bottom Layer w10: J7.1@1005,1210 1031,1184 1031,935.61 v3(1013,917.61)
NetC15_1: C15.1 J14.3 J15.3 R9.2 | length 573.5
  Top Layer w25: C15.1@311,224 R9.2@397,224 J14.3@500,224 573,151 751,151 J15.3@824,224
NetJ4_1: J4.1 U1.D3 | length 378.3
  Signal Layer 2 w10: v2(949.75,905.1) 949.75,1032.75 J4.1@1127,1210
NetJ8_1: J8.1 U1.C2 | length 529.9
  Signal Layer 2 w10: v1(648,1084) 703,1029 800,1029 877,952 877,923.73 911.37,889.36 v2(934,889.36)
  Bottom Layer w10: J8.1@598,1210 598,1134 v1(648,1084)
NetJ10_2: J10.2 U5.C4 | length 893
  Signal Layer 2 w10: v2(867.87,674.54) 867.87,223.68 936.55,155 1184,155 J10.2@1253,224
NetJ12_2: J12.2 U4.B1 | length 589.2
  Signal Layer 2 w10: J12.2@500,443 670,613 670,781.51 702.83,814.34 773.66,814.34 809.43,850.11 v2(821.89,850.11)
NetJ13_2: J13.2 U3.C2 | length 649.5
  Signal Layer 2 w10: v2(958.72,761) 1182,761 v1(1212,791) ; v1@1207.5,795.5 v1@1212,800
  Bottom Layer w10: v1(1212,791) 1212,969 J13.2@1353,1110
NetJ14_2: J14.2 U5.C2 | length 702.8
  Signal Layer 2 w8: 843.86,741 874,741 883.62,731.38 883.62,706.04 v2(867.87,706.04)
  Signal Layer 2 w10: J14.2@600,224 600,321 773,494 773,670.14 843.86,741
